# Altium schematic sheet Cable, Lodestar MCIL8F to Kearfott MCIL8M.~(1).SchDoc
size B; Organization: Monterey Bay Aquarium Research Institute; Address1: 7700 Sandholdt Rd; Address2: Moss Landing, CA 95039-9644; CompanyName: MBARI
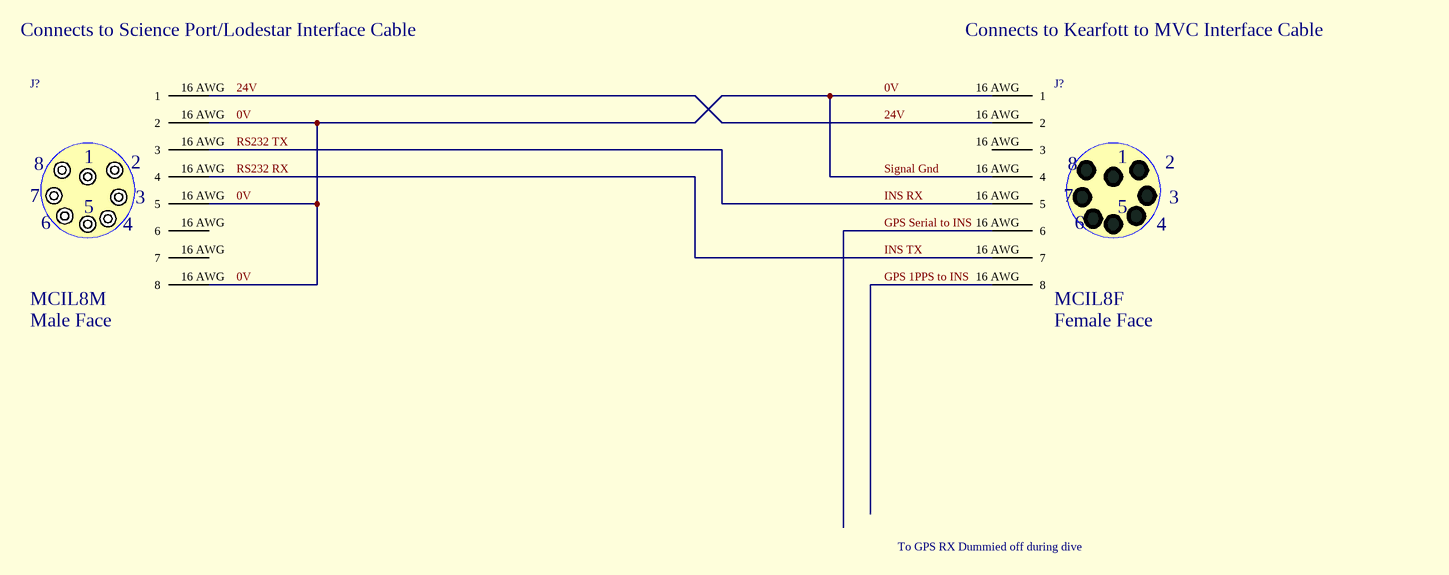
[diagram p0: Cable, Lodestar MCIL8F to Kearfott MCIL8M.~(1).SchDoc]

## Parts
(Parts that share a designator on the sheet are numbered #1, #2 ... from top to bottom, then left to right.)
J?#1  MCIL8M  View: Male Face
J?#2  MCIL8F  View: Female Face

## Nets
0V: J?#1.16_AWG(2) J?#2.16_AWG(1)  [also labelled Signal Gnd]
24V: J?#1.16_AWG(1) J?#2.16_AWG(2)
GPS 1PPS to INS: J?#2.16_AWG(8)
GPS Serial to INS: J?#2.16_AWG(6)
INS RX: J?#1.16_AWG(3) J?#2.16_AWG(5)  [also labelled RS232 TX]
INS TX: J?#1.16_AWG(4) J?#2.16_AWG(7)  [also labelled RS232 RX]

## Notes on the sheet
- Connects to Science Port/Lodestar Interface Cable
- Connects to Kearfott to MVC Interface Cable
- To GPS RX Dummied off during dive

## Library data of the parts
J?#1 = SUBCONN-MCxx8M: Subconn MCIL8M Connector
J?#2 = SUBCONN-MCxx8F: Subconn MCIL8F Connector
